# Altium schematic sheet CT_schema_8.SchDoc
size 274 x 160 mm
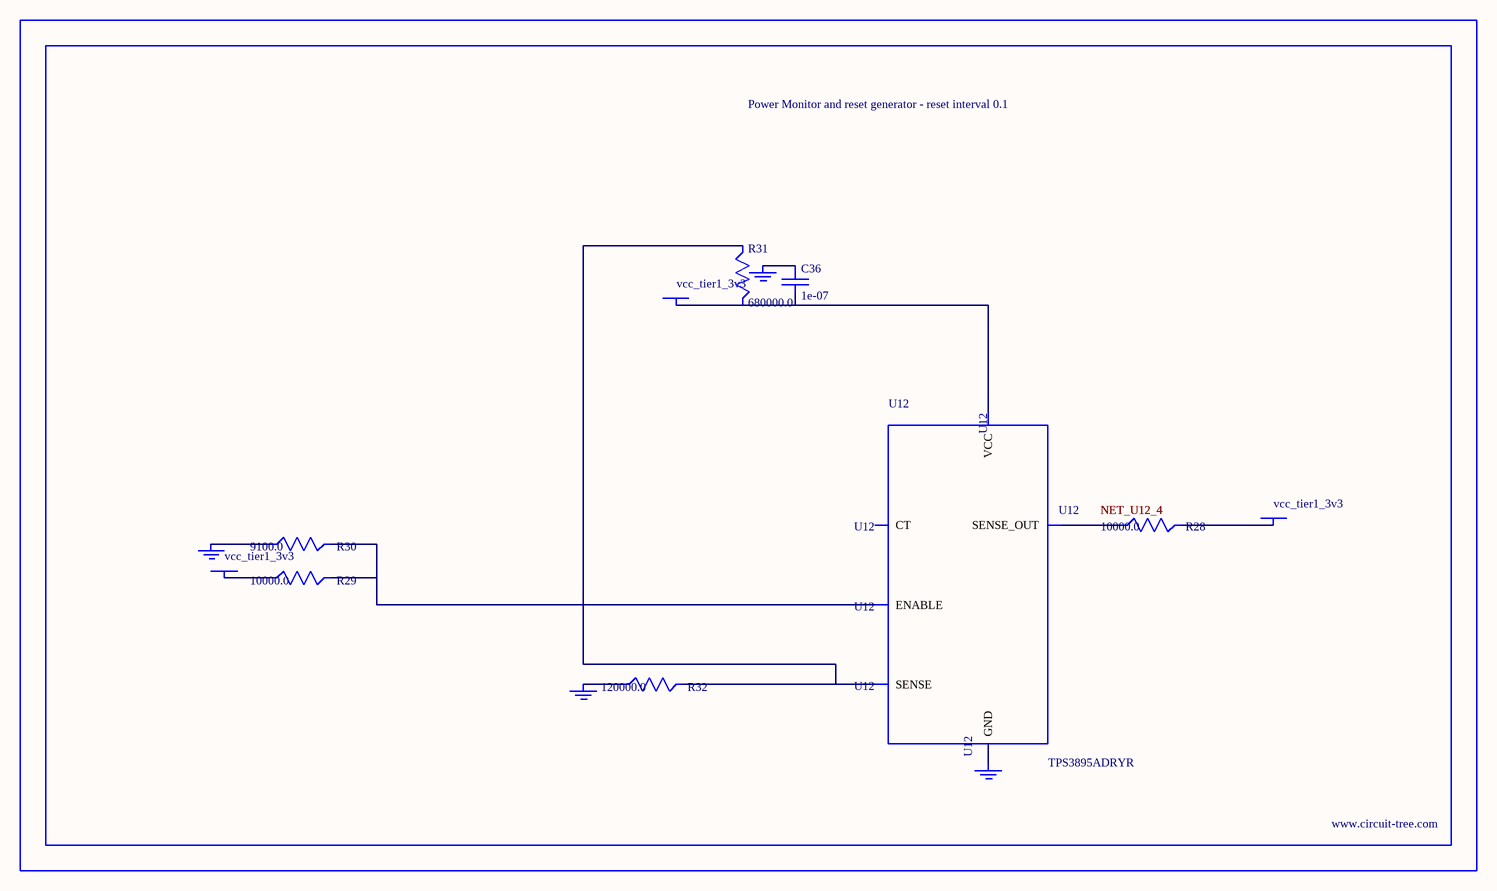
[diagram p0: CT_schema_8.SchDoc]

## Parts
BORDER7  (no value)
C36  1e-07  [C0402]
GND_INSTANCE_7_0  (no value)
GND_INSTANCE_7_1  (no value)
GND_INSTANCE_7_2  (no value)
GND_INSTANCE_7_3  (no value)
POWER_INSTANCE_7_0  vcc_tier1_3v3
POWER_INSTANCE_7_1  vcc_tier1_3v3
POWER_INSTANCE_7_2  vcc_tier1_3v3
R28  10000.0  [R0603]
R29  10000.0  [R0603]
R30  9100.0  [R0603]
R31  680000.0  [R0603]
R32  120000.0  [R0603]
U12  TPS3895ADRYR  [SON-6]

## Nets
NetC36_1: C36.1 GND_INSTANCE_7_2.0(GND)
NetC36_2: C36.2 POWER_INSTANCE_7_2.0(PWR) R31.2 U12.6(VCC)
NetGND_INSTANCE_7_0_0: GND_INSTANCE_7_0.0(GND) R30.1
NetGND_INSTANCE_7_1_0: GND_INSTANCE_7_1.0(GND) R32.1
NetGND_INSTANCE_7_3_0: GND_INSTANCE_7_3.0(GND) U12.2(GND)
NetPOWER_INSTANCE_7_0_0: POWER_INSTANCE_7_0.0(PWR) R29.1
NetPOWER_INSTANCE_7_1_0: POWER_INSTANCE_7_1.0(PWR) R28.2
NetR28_1: R28.1 U12.4(SENSE_OUT)
NetR29_2: R29.2 R30.2 U12.1(ENABLE)
NetR31_1: R31.1 R32.2 U12.3(SENSE)

Not connected (* = marked no-connect by the designer): U12 5(CT)

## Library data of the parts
BORDER7 = BORDER_PAGE7
C36 = C0402C104K3RACTU
GND_INSTANCE_7_0-GND_INSTANCE_7_3 = GND
POWER_INSTANCE_7_0-POWER_INSTANCE_7_2 = PWR
R28 R29 = RC0603JR-0710KL
R30 = RC0603JR-079K1L
R31 = RC0603JR-07680KL
R32 = RC0603JR-07120KL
